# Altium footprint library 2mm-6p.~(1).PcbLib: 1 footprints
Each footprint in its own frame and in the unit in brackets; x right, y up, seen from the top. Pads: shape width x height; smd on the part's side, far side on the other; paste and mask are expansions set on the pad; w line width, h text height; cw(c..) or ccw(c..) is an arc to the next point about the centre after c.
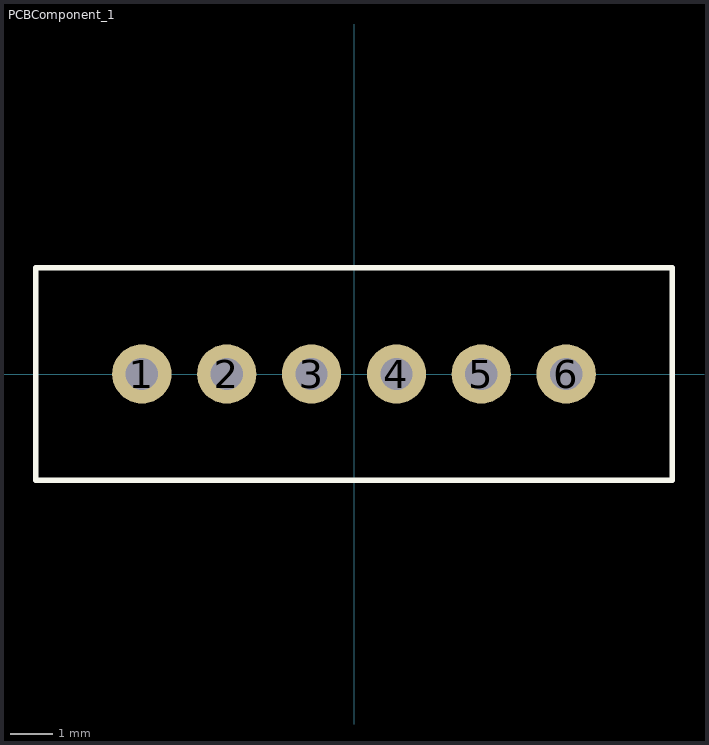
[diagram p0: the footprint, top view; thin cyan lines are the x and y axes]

## PCBComponent_1 [mil]
pads (6):
  round 55 hole 30: 1(-196.85,0) 2(-118.11,0) 3(-39.37,0) 4(39.37,0) 5(118.11,0) 6(196.85,0)
Top Overlay:
  lines w5: -295.28,-98.43 295.28,-98.43 295.28,98.43 -295.28,98.43 -295.28,-98.43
